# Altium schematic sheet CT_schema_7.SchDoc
size 253 x 245 mm
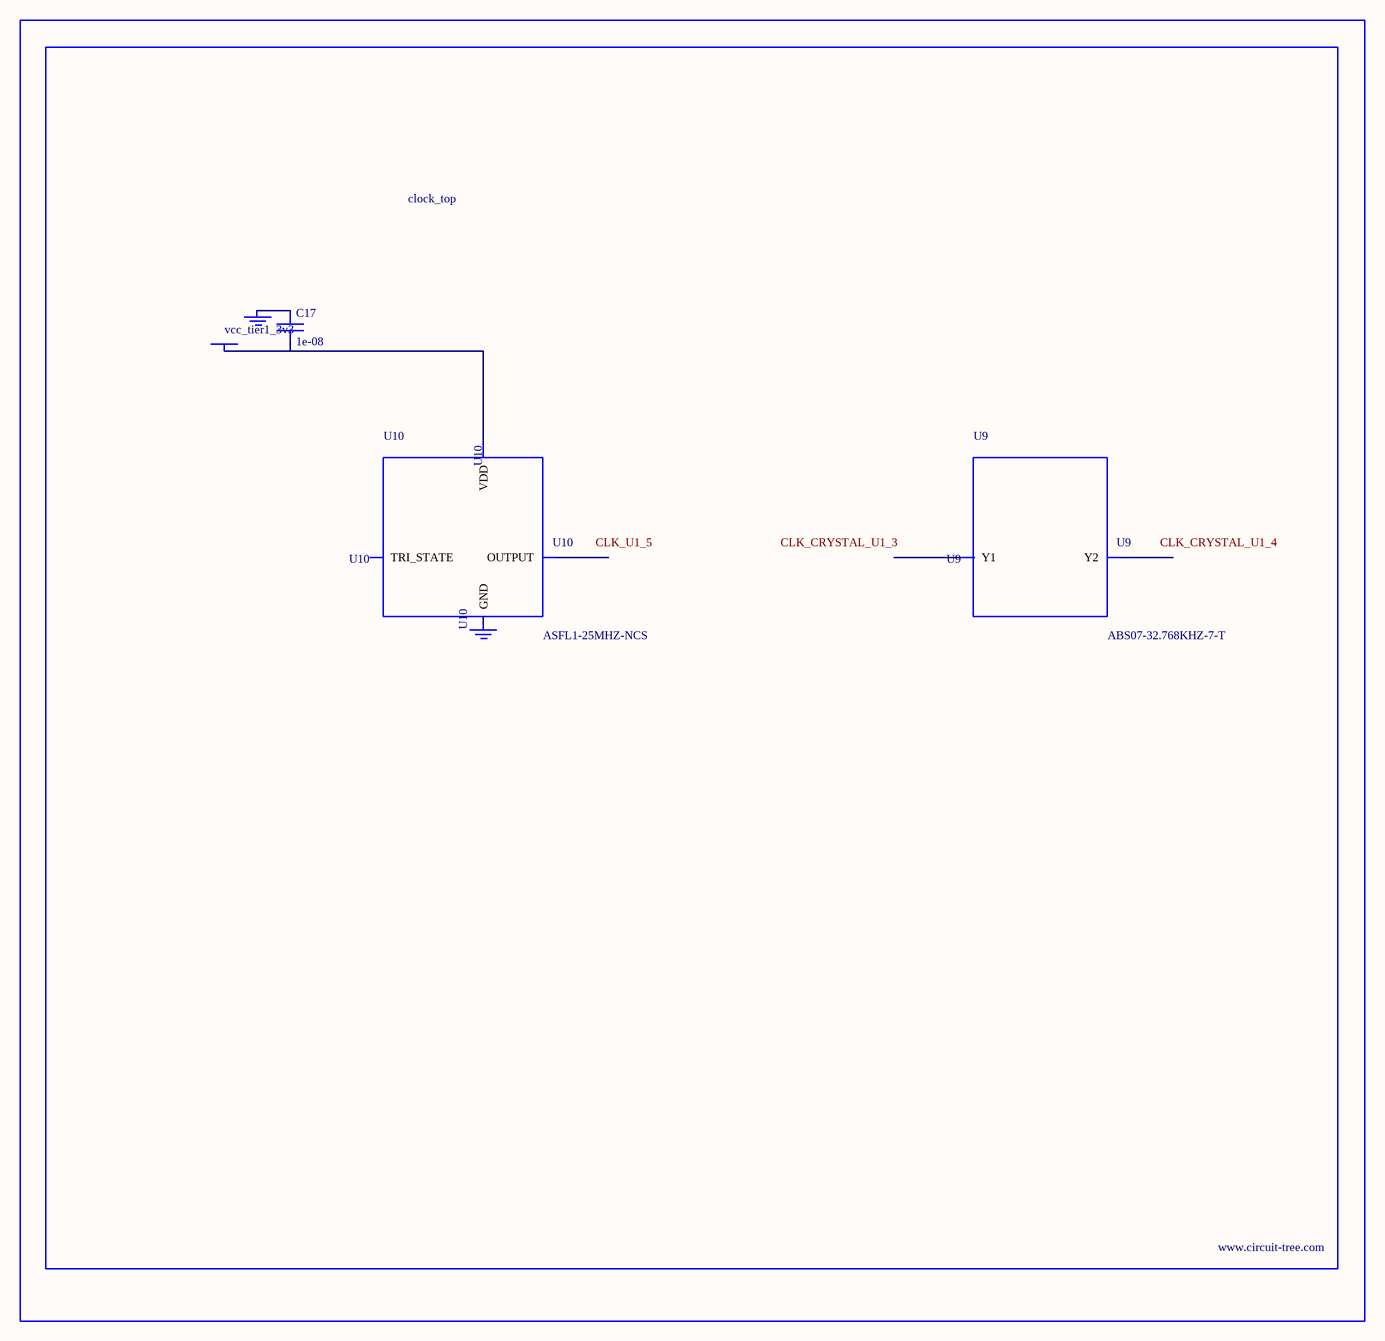
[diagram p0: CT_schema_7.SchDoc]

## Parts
BORDER6  (no value)
C17  1e-08  [C0402]
GND_INSTANCE_6_0  (no value)
GND_INSTANCE_6_1  (no value)
POWER_INSTANCE_6_0  vcc_tier1_3v3
U9  ABS07-32.768KHZ-7-T  [ABS07-32.768KHZ-7-T]
U10  ASFL1-25MHZ-NCS  [ASFL1]

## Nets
NetC17_1: C17.1 GND_INSTANCE_6_0.0(GND)
NetC17_2: C17.2 POWER_INSTANCE_6_0.0(PWR) U10.4(VDD)

Not connected (* = marked no-connect by the designer): GND_INSTANCE_6_1 0(GND); U9 1(Y1) 2(Y2); U10 1(TRI_STATE) 2(GND) 3(OUTPUT)

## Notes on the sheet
- Labels drawn without touching a wire or pin: CLK_CRYSTAL_U1_3, CLK_CRYSTAL_U1_4, CLK_U1_5

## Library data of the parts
BORDER6 = BORDER_PAGE6
C17 = C0402C103K3RAC
GND_INSTANCE_6_0 GND_INSTANCE_6_1 = GND
POWER_INSTANCE_6_0 = PWR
